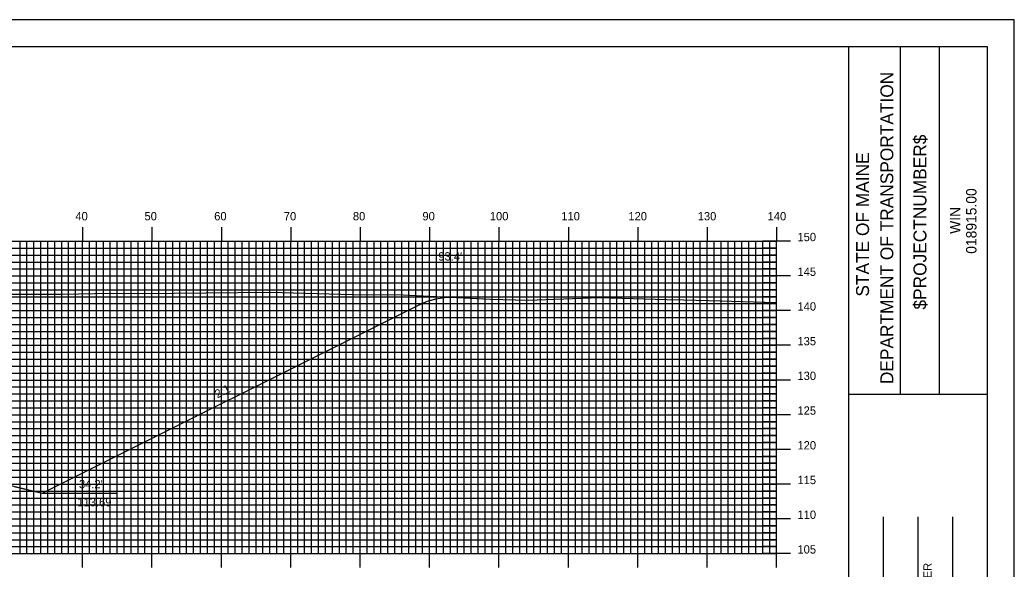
# Model space of a CAD drawing. Extents: x 1768874 to 1769217, y 442591 to 442811.
# Drawn here: x 1769071 to 1769214.2, y 442731.4 to 442810.5 of the extents above; entities that cross this region are included whole.
import ezdxf

# ---------------------------------------------------------------- set-up
doc = ezdxf.new("R2010")
doc.units = 0
for name, color, linetype in [('ANNOTATION', 7, 'Continuous'), ('BORDER', 7, 'Continuous'), ('D_Roadway_Centerline', 7, 'Continuous'), ('D_Roadway_SlopeLines', 7, 'Continuous'), ('D_Text_Standard', 7, 'Continuous'), ('H_V ANNOTATION', 7, 'Continuous'), ('MAJOR', 7, 'Continuous'), ('MINOR', 7, 'Continuous'), ('PDRAIN', 7, 'Continuous'), ('PLOT BOUNDARY', 7, 'Continuous'), ('S_Roadway_Centerline', 7, 'Continuous')]:
    doc.layers.add(name, color=color, linetype=linetype)

msp = doc.modelspace()

# ---------------------------------------------------------------- linework, layer by layer
at = {"layer": 'BORDER'}
for p, q in [((1769190.39, 442596.67), (1769190.39, 442806.67)), ((1769197.85, 442756.66), (1769197.85, 442806.66)), ((1769203.44, 442756.66), (1769203.44, 442806.66)), ((1769190.39, 442756.65), (1769210.39, 442756.65)), ((1769195.39, 442721.67), (1769195.39, 442738.97)), ((1769200.39, 442721.67), (1769200.39, 442738.97)), ((1769205.39, 442721.67), (1769205.39, 442738.97))]:
    msp.add_line(p, q, dxfattribs=at)
msp.add_lwpolyline([(1768890.39, 442596.67), (1769210.39, 442596.67), (1769210.39, 442806.67), (1768890.39, 442806.67)], close=True, dxfattribs=at)
at = {"layer": 'D_Roadway_Centerline'}
msp.add_lwpolyline([(1769070.16, 442743.35), (1769074.16, 442742.35), (1769074.16, 442742.35), (1769128.39, 442769.47), (1769129.2, 442769.81), (1769129.64, 442770.01), (1769130.28, 442770.19), (1769130.89, 442770.37), (1769132.09, 442770.56), (1769132.14, 442770.57), (1769133.39, 442770.59)], dxfattribs=at)
at = {"layer": 'D_Roadway_SlopeLines'}
for points in [[(1769074.16, 442742.35), (1769128.39, 442769.47), (1769129.64, 442770.01), (1769130.89, 442770.37), (1769132.14, 442770.57), (1769133.39, 442770.59)], [(1769059.99, 442745.9), (1769074.16, 442742.35)]]:
    msp.add_lwpolyline(points, dxfattribs=at)
at = {"layer": 'MAJOR'}
for p, q in [((1769079.99, 442780.67), (1769079.99, 442778.67)), ((1769089.99, 442780.67), (1769089.99, 442778.67)), ((1769099.99, 442780.67), (1769099.99, 442778.67)), ((1769109.99, 442780.67), (1769109.99, 442778.67)), ((1769119.99, 442780.67), (1769119.99, 442778.67)), ((1769129.99, 442780.67), (1769129.99, 442778.67)), ((1769139.99, 442780.67), (1769139.99, 442778.67)), ((1769149.99, 442780.67), (1769149.99, 442778.67)), ((1769159.99, 442780.67), (1769159.99, 442778.67)), ((1769169.99, 442780.67), (1769169.99, 442778.67)), ((1769179.99, 442780.67), (1769179.99, 442778.67)), ((1768899.99, 442778.67), (1769179.99, 442778.67)), ((1768899.99, 442778.67), (1769179.99, 442778.67)), ((1769079.99, 442733.67), (1769079.99, 442778.67)), ((1769089.99, 442733.67), (1769089.99, 442778.67)), ((1769099.99, 442733.67), (1769099.99, 442778.67)), ((1769109.99, 442733.67), (1769109.99, 442778.67)), ((1769119.99, 442733.67), (1769119.99, 442778.67)), ((1769129.99, 442733.67), (1769129.99, 442778.67)), ((1769139.99, 442733.67), (1769139.99, 442778.67)), ((1769149.99, 442733.67), (1769149.99, 442778.67)), ((1769159.99, 442733.67), (1769159.99, 442778.67)), ((1769169.99, 442733.67), (1769169.99, 442778.67)), ((1769181.99, 442778.67), (1769177.98, 442778.67)), ((1769179.99, 442733.67), (1769179.99, 442778.67)), ((1769179.99, 442733.67), (1769179.99, 442778.67)), ((1768899.99, 442773.67), (1769179.99, 442773.67)), ((1769181.99, 442773.67), (1769177.98, 442773.67)), ((1768899.99, 442768.67), (1769179.99, 442768.67)), ((1769181.99, 442768.67), (1769177.98, 442768.67)), ((1768899.99, 442763.67), (1769179.99, 442763.67)), ((1769181.99, 442763.67), (1769177.98, 442763.67)), ((1768899.99, 442758.67), (1769179.99, 442758.67)), ((1769181.99, 442758.67), (1769177.98, 442758.67)), ((1768899.99, 442753.67), (1769179.99, 442753.67)), ((1769181.99, 442753.67), (1769177.98, 442753.67)), ((1768899.99, 442748.67), (1769179.99, 442748.67)), ((1769181.99, 442748.67), (1769177.98, 442748.67)), ((1768899.99, 442743.67), (1769179.99, 442743.67)), ((1769181.99, 442743.67), (1769177.98, 442743.67)), ((1768899.99, 442738.67), (1769179.99, 442738.67)), ((1769181.99, 442738.67), (1769177.98, 442738.67)), ((1768899.99, 442733.67), (1769179.99, 442733.67)), ((1768899.99, 442733.67), (1769179.99, 442733.67)), ((1769079.99, 442731.66), (1769079.99, 442733.67)), ((1769089.99, 442731.66), (1769089.99, 442733.67)), ((1769099.99, 442731.66), (1769099.99, 442733.67)), ((1769109.99, 442731.66), (1769109.99, 442733.67)), ((1769119.99, 442731.66), (1769119.99, 442733.67)), ((1769129.99, 442731.66), (1769129.99, 442733.67)), ((1769139.99, 442731.66), (1769139.99, 442733.67)), ((1769149.99, 442731.66), (1769149.99, 442733.67)), ((1769159.99, 442731.66), (1769159.99, 442733.67)), ((1769169.99, 442731.66), (1769169.99, 442733.67)), ((1769181.99, 442733.67), (1769177.98, 442733.67)), ((1769179.99, 442731.66), (1769179.99, 442733.67))]:
    msp.add_line(p, q, dxfattribs=at)
at = {"layer": 'MINOR'}
for p, q in [((1769070.99, 442733.67), (1769070.99, 442778.67)), ((1769071.99, 442733.67), (1769071.99, 442778.67)), ((1769072.99, 442733.67), (1769072.99, 442778.67)), ((1769073.99, 442733.67), (1769073.99, 442778.67)), ((1769074.99, 442733.67), (1769074.99, 442778.67)), ((1769075.99, 442733.67), (1769075.99, 442778.67)), ((1769076.99, 442733.67), (1769076.99, 442778.67)), ((1769077.99, 442733.67), (1769077.99, 442778.67)), ((1769078.99, 442733.67), (1769078.99, 442778.67)), ((1769080.99, 442733.67), (1769080.99, 442778.67)), ((1769081.99, 442733.67), (1769081.99, 442778.67)), ((1769082.99, 442733.67), (1769082.99, 442778.67)), ((1769083.99, 442733.67), (1769083.99, 442778.67)), ((1769084.99, 442733.67), (1769084.99, 442778.67)), ((1769085.99, 442733.67), (1769085.99, 442778.67)), ((1769086.99, 442733.67), (1769086.99, 442778.67)), ((1769087.99, 442733.67), (1769087.99, 442778.67)), ((1769088.99, 442733.67), (1769088.99, 442778.67)), ((1769090.99, 442733.67), (1769090.99, 442778.67)), ((1769091.99, 442733.67), (1769091.99, 442778.67)), ((1769092.99, 442733.67), (1769092.99, 442778.67)), ((1769093.99, 442733.67), (1769093.99, 442778.67)), ((1769094.99, 442733.67), (1769094.99, 442778.67)), ((1769095.99, 442733.67), (1769095.99, 442778.67)), ((1769096.99, 442733.67), (1769096.99, 442778.67)), ((1769097.99, 442733.67), (1769097.99, 442778.67)), ((1769098.99, 442733.67), (1769098.99, 442778.67)), ((1769100.99, 442733.67), (1769100.99, 442778.67)), ((1769101.99, 442733.67), (1769101.99, 442778.67)), ((1769102.99, 442733.67), (1769102.99, 442778.67)), ((1769103.99, 442733.67), (1769103.99, 442778.67)), ((1769104.99, 442733.67), (1769104.99, 442778.67)), ((1769105.99, 442733.67), (1769105.99, 442778.67)), ((1769106.99, 442733.67), (1769106.99, 442778.67)), ((1769107.99, 442733.67), (1769107.99, 442778.67)), ((1769108.99, 442733.67), (1769108.99, 442778.67)), ((1769110.99, 442733.67), (1769110.99, 442778.67)), ((1769111.99, 442733.67), (1769111.99, 442778.67)), ((1769112.99, 442733.67), (1769112.99, 442778.67)), ((1769113.99, 442733.67), (1769113.99, 442778.67)), ((1769114.99, 442733.67), (1769114.99, 442778.67)), ((1769115.99, 442733.67), (1769115.99, 442778.67)), ((1769116.99, 442733.67), (1769116.99, 442778.67)), ((1769117.99, 442733.67), (1769117.99, 442778.67)), ((1769118.99, 442733.67), (1769118.99, 442778.67)), ((1769120.99, 442733.67), (1769120.99, 442778.67)), ((1769121.99, 442733.67), (1769121.99, 442778.67)), ((1769122.99, 442733.67), (1769122.99, 442778.67)), ((1769123.99, 442733.67), (1769123.99, 442778.67)), ((1769124.99, 442733.67), (1769124.99, 442778.67)), ((1769125.99, 442733.67), (1769125.99, 442778.67)), ((1769126.99, 442733.67), (1769126.99, 442778.67)), ((1769127.99, 442733.67), (1769127.99, 442778.67)), ((1769128.99, 442733.67), (1769128.99, 442778.67)), ((1769130.99, 442733.67), (1769130.99, 442778.67)), ((1769131.99, 442733.67), (1769131.99, 442778.67)), ((1769132.99, 442733.67), (1769132.99, 442778.67)), ((1769133.99, 442733.67), (1769133.99, 442778.67)), ((1769134.99, 442733.67), (1769134.99, 442778.67)), ((1769135.99, 442733.67), (1769135.99, 442778.67)), ((1769136.99, 442733.67), (1769136.99, 442778.67)), ((1769137.99, 442733.67), (1769137.99, 442778.67)), ((1769138.99, 442733.67), (1769138.99, 442778.67)), ((1769140.99, 442733.67), (1769140.99, 442778.67)), ((1769141.99, 442733.67), (1769141.99, 442778.67)), ((1769142.99, 442733.67), (1769142.99, 442778.67)), ((1769143.99, 442733.67), (1769143.99, 442778.67)), ((1769144.99, 442733.67), (1769144.99, 442778.67)), ((1769145.99, 442733.67), (1769145.99, 442778.67)), ((1769146.99, 442733.67), (1769146.99, 442778.67)), ((1769147.99, 442733.67), (1769147.99, 442778.67)), ((1769148.99, 442733.67), (1769148.99, 442778.67)), ((1769150.99, 442733.67), (1769150.99, 442778.67)), ((1769151.99, 442733.67), (1769151.99, 442778.67)), ((1769152.99, 442733.67), (1769152.99, 442778.67)), ((1769153.99, 442733.67), (1769153.99, 442778.67)), ((1769154.99, 442733.67), (1769154.99, 442778.67)), ((1769155.99, 442733.67), (1769155.99, 442778.67)), ((1769156.99, 442733.67), (1769156.99, 442778.67)), ((1769157.99, 442733.67), (1769157.99, 442778.67)), ((1769158.99, 442733.67), (1769158.99, 442778.67)), ((1769160.99, 442733.67), (1769160.99, 442778.67)), ((1769161.99, 442733.67), (1769161.99, 442778.67)), ((1769162.99, 442733.67), (1769162.99, 442778.67)), ((1769163.99, 442733.67), (1769163.99, 442778.67)), ((1769164.99, 442733.67), (1769164.99, 442778.67)), ((1769165.99, 442733.67), (1769165.99, 442778.67)), ((1769166.99, 442733.67), (1769166.99, 442778.67)), ((1769167.99, 442733.67), (1769167.99, 442778.67)), ((1769168.99, 442733.67), (1769168.99, 442778.67)), ((1769170.99, 442733.67), (1769170.99, 442778.67)), ((1769171.99, 442733.67), (1769171.99, 442778.67)), ((1769172.99, 442733.67), (1769172.99, 442778.67)), ((1769173.99, 442733.67), (1769173.99, 442778.67)), ((1769174.99, 442733.67), (1769174.99, 442778.67)), ((1769175.99, 442733.67), (1769175.99, 442778.67)), ((1769176.99, 442733.67), (1769176.99, 442778.67)), ((1769177.99, 442733.67), (1769177.99, 442778.67)), ((1769178.99, 442733.67), (1769178.99, 442778.67)), ((1768899.99, 442777.67), (1769179.99, 442777.67)), ((1769179.99, 442777.67), (1769177.98, 442777.67)), ((1768899.99, 442776.67), (1769179.99, 442776.67)), ((1768899.99, 442775.67), (1769179.99, 442775.67)), ((1769179.99, 442776.67), (1769177.98, 442776.67)), ((1769179.99, 442775.67), (1769177.98, 442775.67)), ((1768899.99, 442774.67), (1769179.99, 442774.67)), ((1769179.99, 442774.67), (1769177.98, 442774.67)), ((1768899.99, 442772.67), (1769179.99, 442772.67)), ((1769179.99, 442772.67), (1769177.98, 442772.67)), ((1768899.99, 442771.67), (1769179.99, 442771.67)), ((1769179.99, 442771.67), (1769177.98, 442771.67)), ((1768899.99, 442770.67), (1769179.99, 442770.67)), ((1769179.99, 442770.67), (1769177.98, 442770.67)), ((1768899.99, 442769.67), (1769179.99, 442769.67)), ((1769179.99, 442769.67), (1769177.98, 442769.67)), ((1768899.99, 442767.67), (1769179.99, 442767.67)), ((1769179.99, 442767.67), (1769177.98, 442767.67)), ((1768899.99, 442766.67), (1769179.99, 442766.67)), ((1768899.99, 442765.67), (1769179.99, 442765.67)), ((1769179.99, 442766.67), (1769177.98, 442766.67)), ((1769179.99, 442765.67), (1769177.98, 442765.67)), ((1768899.99, 442764.67), (1769179.99, 442764.67)), ((1769179.99, 442764.67), (1769177.98, 442764.67)), ((1768899.99, 442762.67), (1769179.99, 442762.67)), ((1769179.99, 442762.67), (1769177.98, 442762.67)), ((1768899.99, 442761.67), (1769179.99, 442761.67)), ((1769179.99, 442761.67), (1769177.98, 442761.67)), ((1768899.99, 442760.67), (1769179.99, 442760.67)), ((1769179.99, 442760.67), (1769177.98, 442760.67)), ((1768899.99, 442759.67), (1769179.99, 442759.67)), ((1769179.99, 442759.67), (1769177.98, 442759.67)), ((1768899.99, 442757.67), (1769179.99, 442757.67)), ((1769179.99, 442757.67), (1769177.98, 442757.67)), ((1768899.99, 442756.67), (1769179.99, 442756.67)), ((1768899.99, 442755.67), (1769179.99, 442755.67)), ((1769179.99, 442756.67), (1769177.98, 442756.67)), ((1769179.99, 442755.67), (1769177.98, 442755.67)), ((1768899.99, 442754.67), (1769179.99, 442754.67)), ((1769179.99, 442754.67), (1769177.98, 442754.67)), ((1768899.99, 442752.67), (1769179.99, 442752.67)), ((1769179.99, 442752.67), (1769177.98, 442752.67)), ((1768899.99, 442751.67), (1769179.99, 442751.67)), ((1769179.99, 442751.67), (1769177.98, 442751.67)), ((1768899.99, 442750.67), (1769179.99, 442750.67)), ((1768899.99, 442749.67), (1769179.99, 442749.67)), ((1769179.99, 442750.67), (1769177.98, 442750.67)), ((1769179.99, 442749.67), (1769177.98, 442749.67)), ((1768899.99, 442747.67), (1769179.99, 442747.67)), ((1769179.99, 442747.67), (1769177.98, 442747.67)), ((1768899.99, 442746.67), (1769179.99, 442746.67)), ((1768899.99, 442745.67), (1769179.99, 442745.67)), ((1769179.99, 442746.67), (1769177.98, 442746.67)), ((1769179.99, 442745.67), (1769177.98, 442745.67)), ((1768899.99, 442744.67), (1769179.99, 442744.67)), ((1769179.99, 442744.67), (1769177.98, 442744.67)), ((1768899.99, 442742.67), (1769179.99, 442742.67)), ((1769179.99, 442742.67), (1769177.98, 442742.67)), ((1768899.99, 442741.67), (1769179.99, 442741.67)), ((1769179.99, 442741.67), (1769177.98, 442741.67)), ((1768899.99, 442740.67), (1769179.99, 442740.67)), ((1768899.99, 442739.67), (1769179.99, 442739.67)), ((1769179.99, 442740.67), (1769177.98, 442740.67)), ((1769179.99, 442739.67), (1769177.98, 442739.67)), ((1768899.99, 442737.67), (1769179.99, 442737.67)), ((1769179.99, 442737.67), (1769177.98, 442737.67)), ((1768899.99, 442736.67), (1769179.99, 442736.67)), ((1768899.99, 442735.67), (1769179.99, 442735.67)), ((1769179.99, 442736.67), (1769177.98, 442736.67)), ((1769179.99, 442735.67), (1769177.98, 442735.67)), ((1768899.99, 442734.67), (1769179.99, 442734.67)), ((1769179.99, 442734.67), (1769177.98, 442734.67))]:
    msp.add_line(p, q, dxfattribs=at)
at = {"layer": 'PDRAIN'}
msp.add_line((1769074.16, 442742.35), (1769084.93, 442742.35), dxfattribs=at)
at = {"layer": 'PLOT BOUNDARY'}
msp.add_lwpolyline([(1768874.2, 442590.55), (1769214.2, 442590.55), (1769214.2, 442810.55), (1768874.2, 442810.55)], close=True, dxfattribs=at)
at = {"layer": 'S_Roadway_Centerline'}
msp.add_lwpolyline([(1769068.53, 442771.04), (1769077.1, 442771.05), (1769084.01, 442771.16), (1769088.56, 442771.14), (1769106.92, 442771.32), (1769106.94, 442771.32), (1769106.95, 442771.32), (1769106.96, 442771.32), (1769118.91, 442770.98), (1769126.18, 442770.96), (1769138.71, 442770.32), (1769144.2, 442770.18), (1769154.47, 442770.56), (1769164.15, 442770.26), (1769166.55, 442770.22), (1769170.21, 442770.11), (1769179.99, 442769.82)], dxfattribs=at)

# ---------------------------------------------------------------- texts
at = {"layer": 'ANNOTATION'}
msp.add_text('2:1', height=1.2, rotation=26.5645, dxfattribs=at).set_placement((1769099.42, 442756.02))
for s, p in [("34.2'", (1769079.47, 442743.08)), ('113.69', (1769079.25, 442740.48))]:
    msp.add_text(s, height=1.2, dxfattribs=at).set_placement(p)
at = {"layer": 'BORDER'}
for s, height, p in [('DEPARTMENT OF TRANSPORTATION', 1.8635, (1769196.8, 442758.08)), ('$PROJECTNUMBER$', 1.8635, (1769201.57, 442768.82)), ('STATE OF MAINE', 1.8635, (1769193.3, 442770.69)), ('018915.00', 1.491, (1769208.78, 442776.86)), ('WIN', 1.491, (1769206.46, 442779.73)), ('P.E. NUMBER', 1.1811, (1769202.31, 442722.06))]:
    msp.add_text(s, height=height, rotation=90, dxfattribs=at).set_placement(p)
at = {"layer": 'D_Text_Standard'}
msp.add_text("93.4'", height=1.2, dxfattribs=at).set_placement((1769131.25, 442775.88))
at = {"layer": 'H_V ANNOTATION'}
for s, p in [('40', (1769078.96, 442781.67)), ('50', (1769088.92, 442781.67)), ('60', (1769098.96, 442781.67)), ('70', (1769108.99, 442781.67)), ('80', (1769118.94, 442781.67)), ('90', (1769128.96, 442781.67)), ('100', (1769138.67, 442781.67)), ('110', (1769148.97, 442781.67)), ('120', (1769158.63, 442781.67)), ('130', (1769168.62, 442781.67)), ('140', (1769178.69, 442781.67)), ('150', (1769182.99, 442778.67)), ('145', (1769182.99, 442773.67)), ('140', (1769182.99, 442768.67)), ('135', (1769182.99, 442763.67)), ('130', (1769182.99, 442758.67)), ('125', (1769182.99, 442753.67)), ('120', (1769182.99, 442748.67)), ('115', (1769182.99, 442743.67)), ('110', (1769182.99, 442738.67)), ('105', (1769182.99, 442733.67))]:
    msp.add_text(s, height=1.2, dxfattribs=at).set_placement(p)

doc.saveas('drawing.dxf')
